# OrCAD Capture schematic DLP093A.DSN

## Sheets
1 PAGE-06 Disclaimer
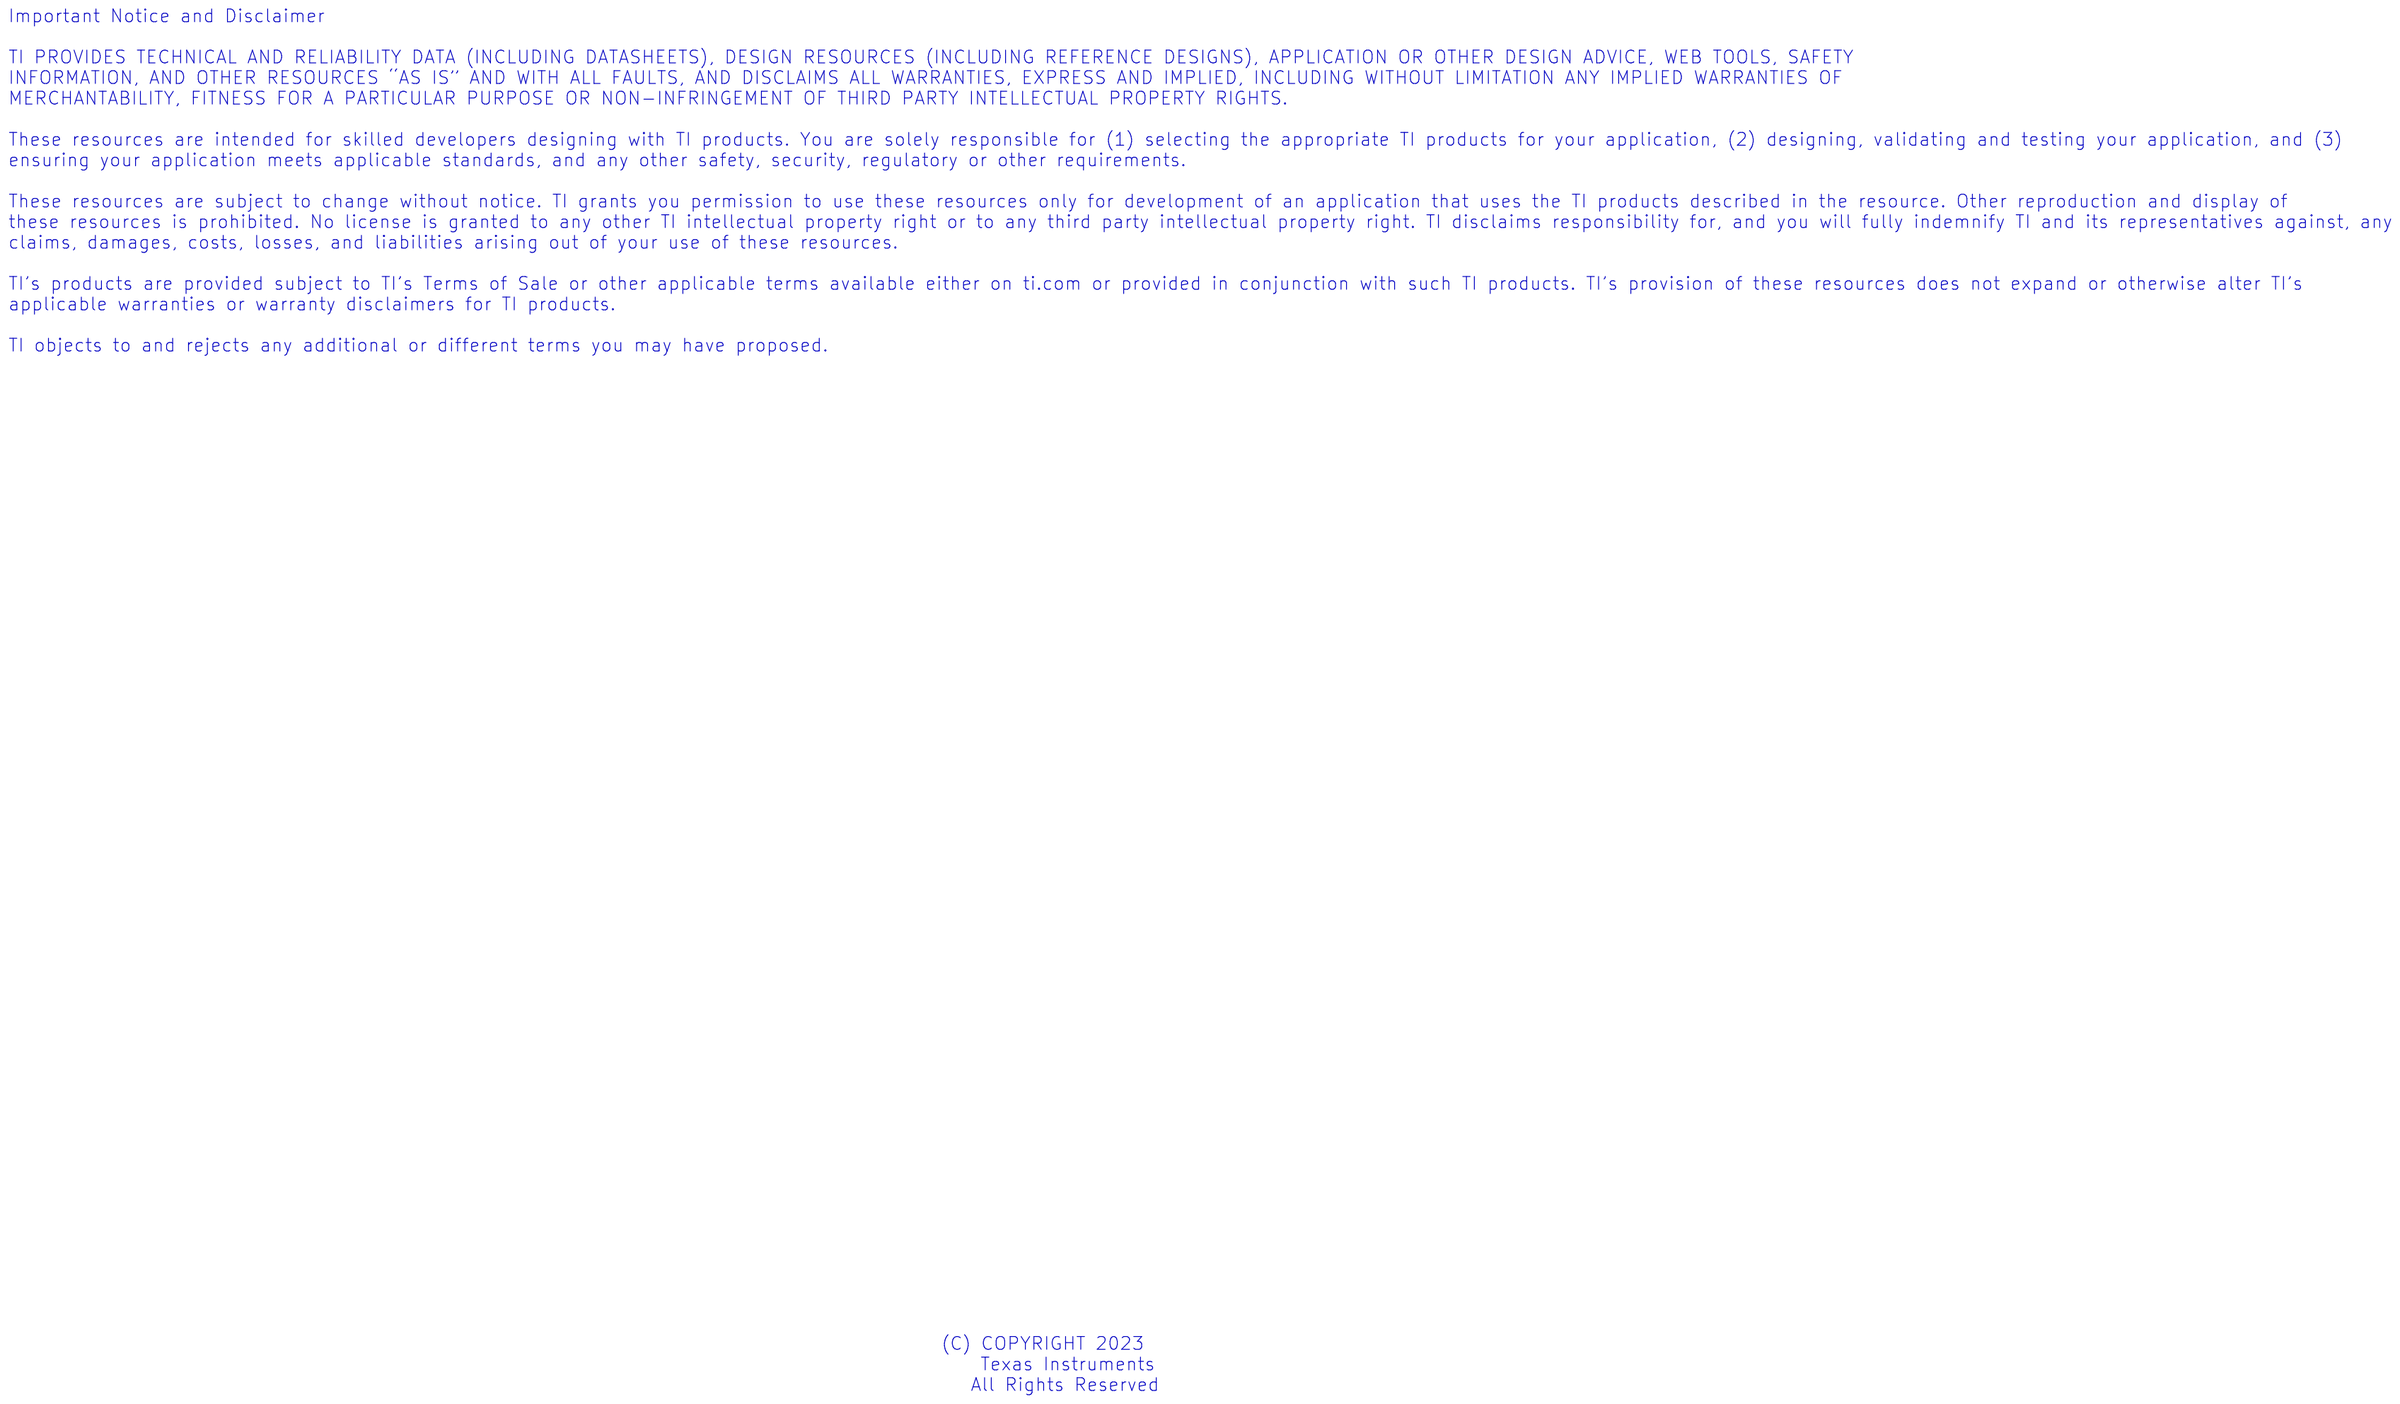
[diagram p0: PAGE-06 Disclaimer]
2 PAGE-05  DLPA200 RESET DRIVER: size A3
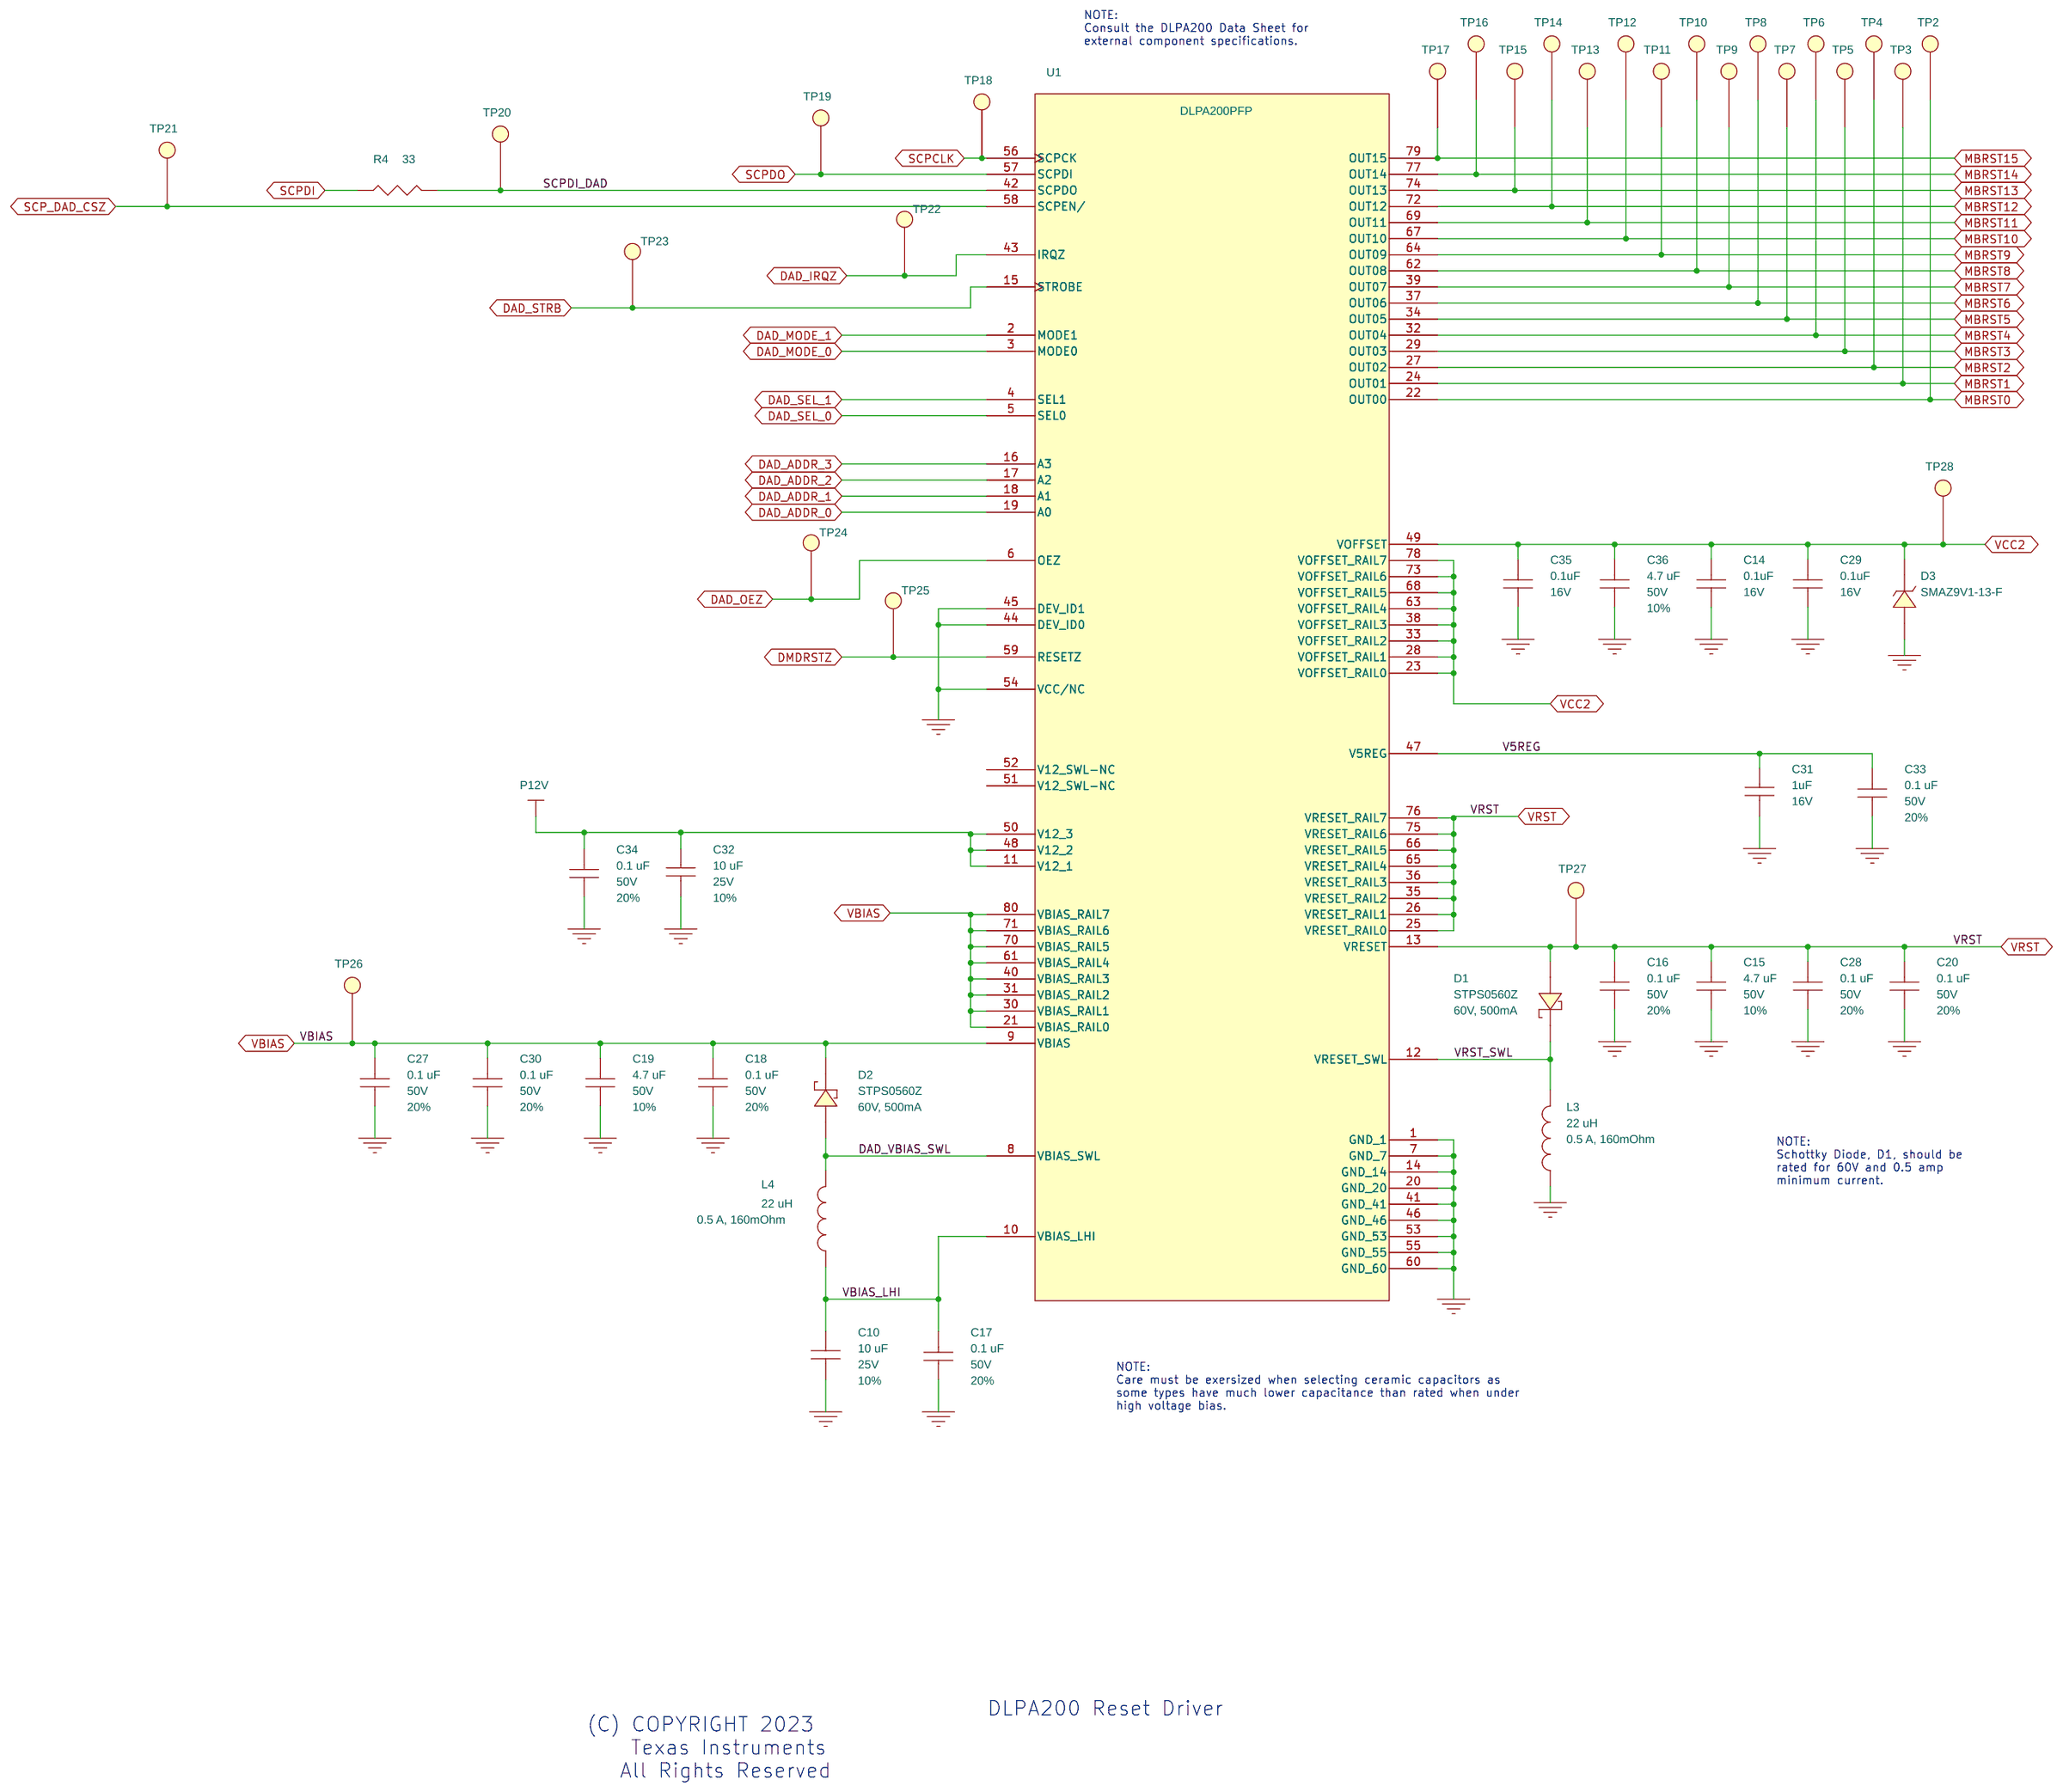
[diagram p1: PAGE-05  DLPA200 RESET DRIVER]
3 PAGE-01  TITLE
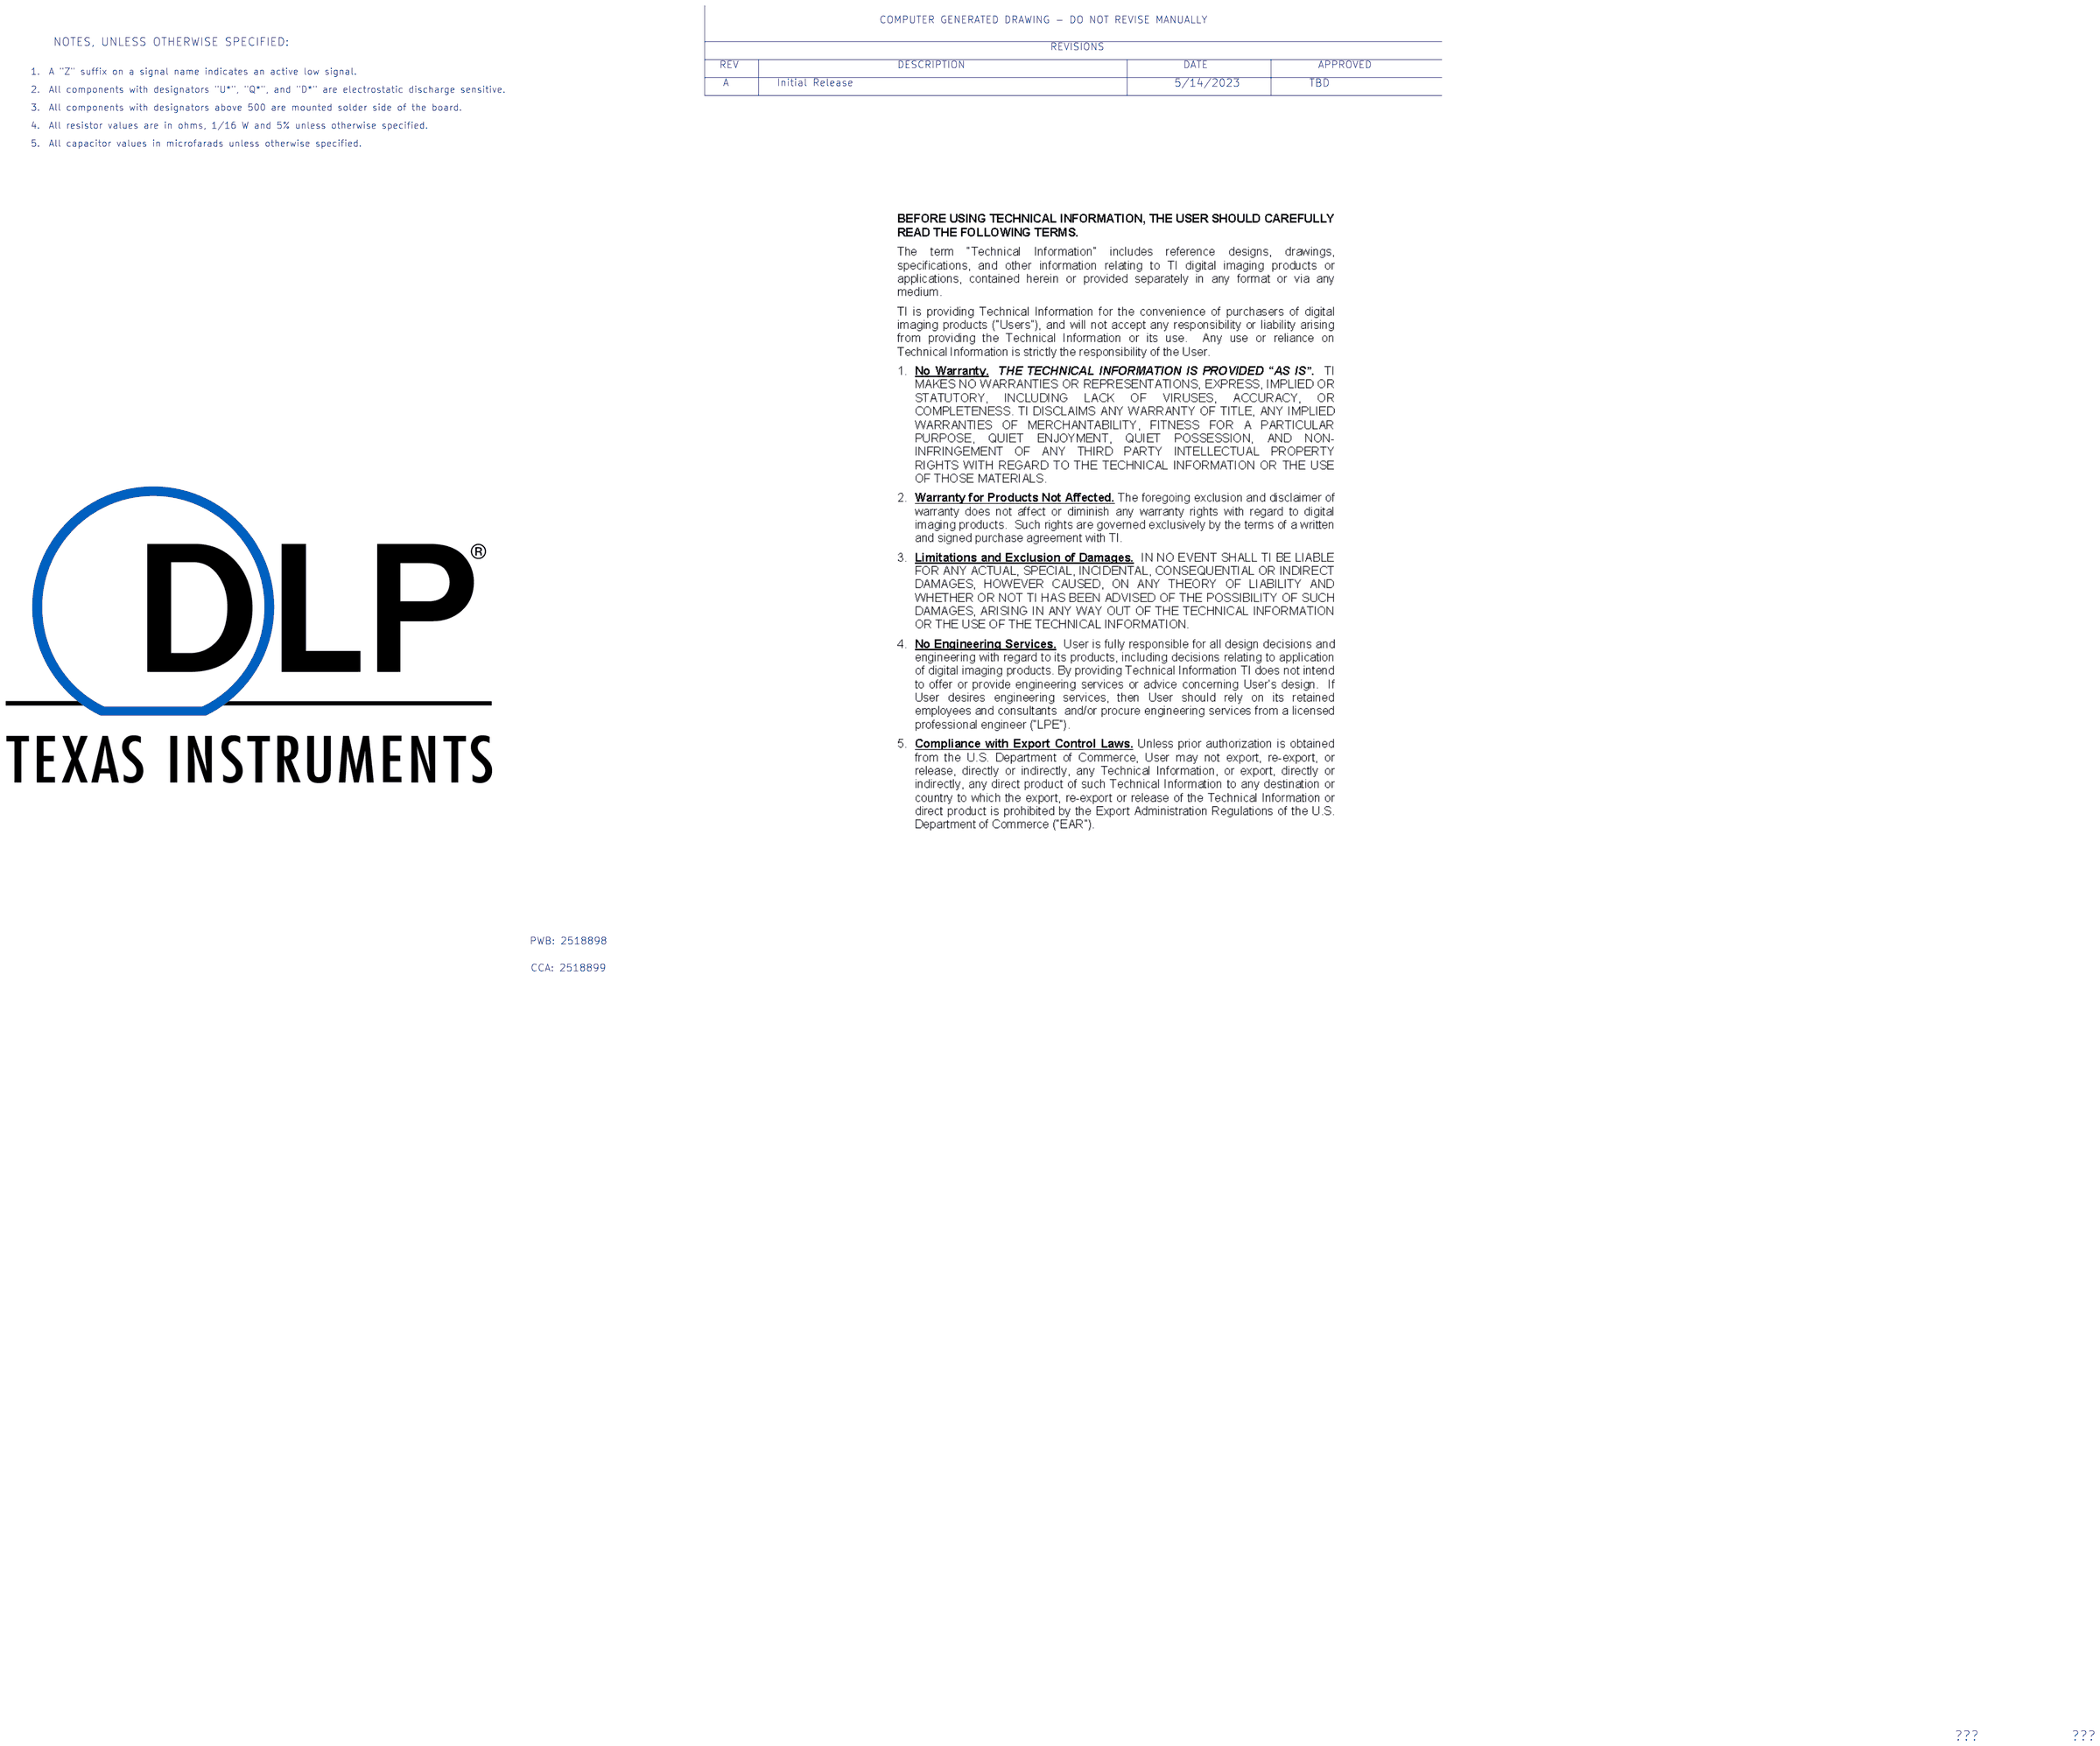
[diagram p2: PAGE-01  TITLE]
4 PAGE-02  Block Diagram
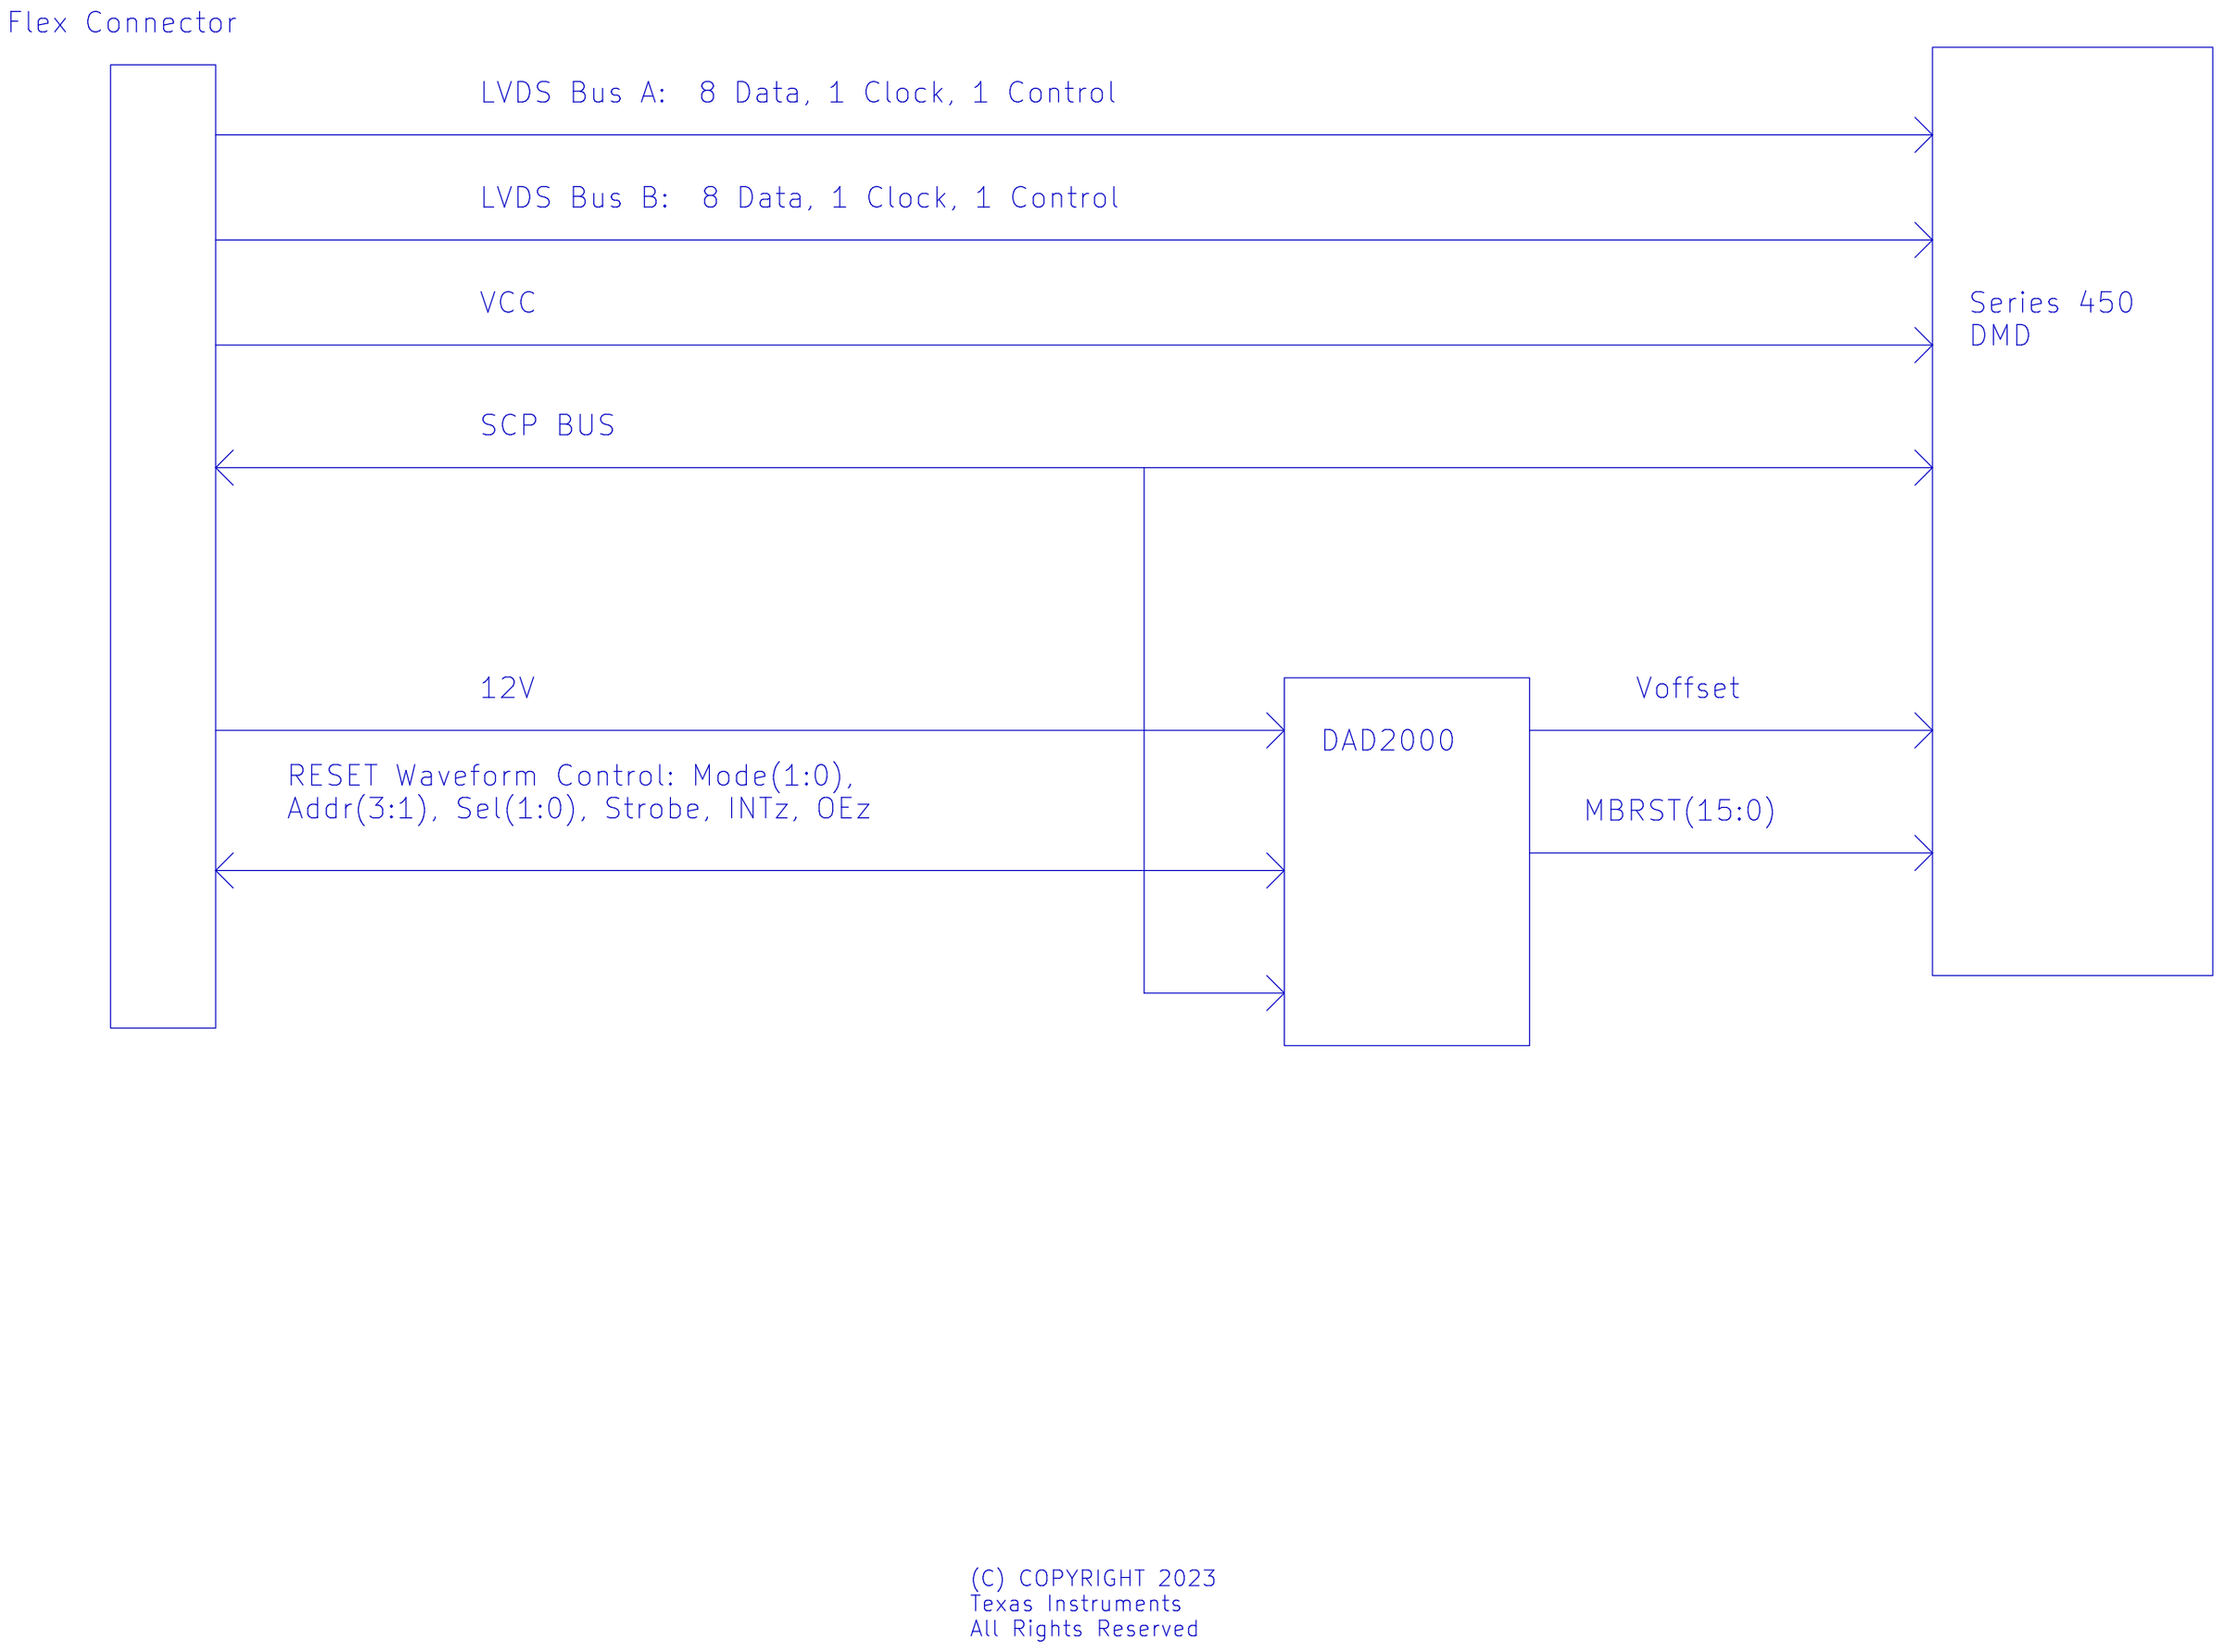
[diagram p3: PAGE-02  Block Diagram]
5 PAGE-04  Series 450 DMD: size A3
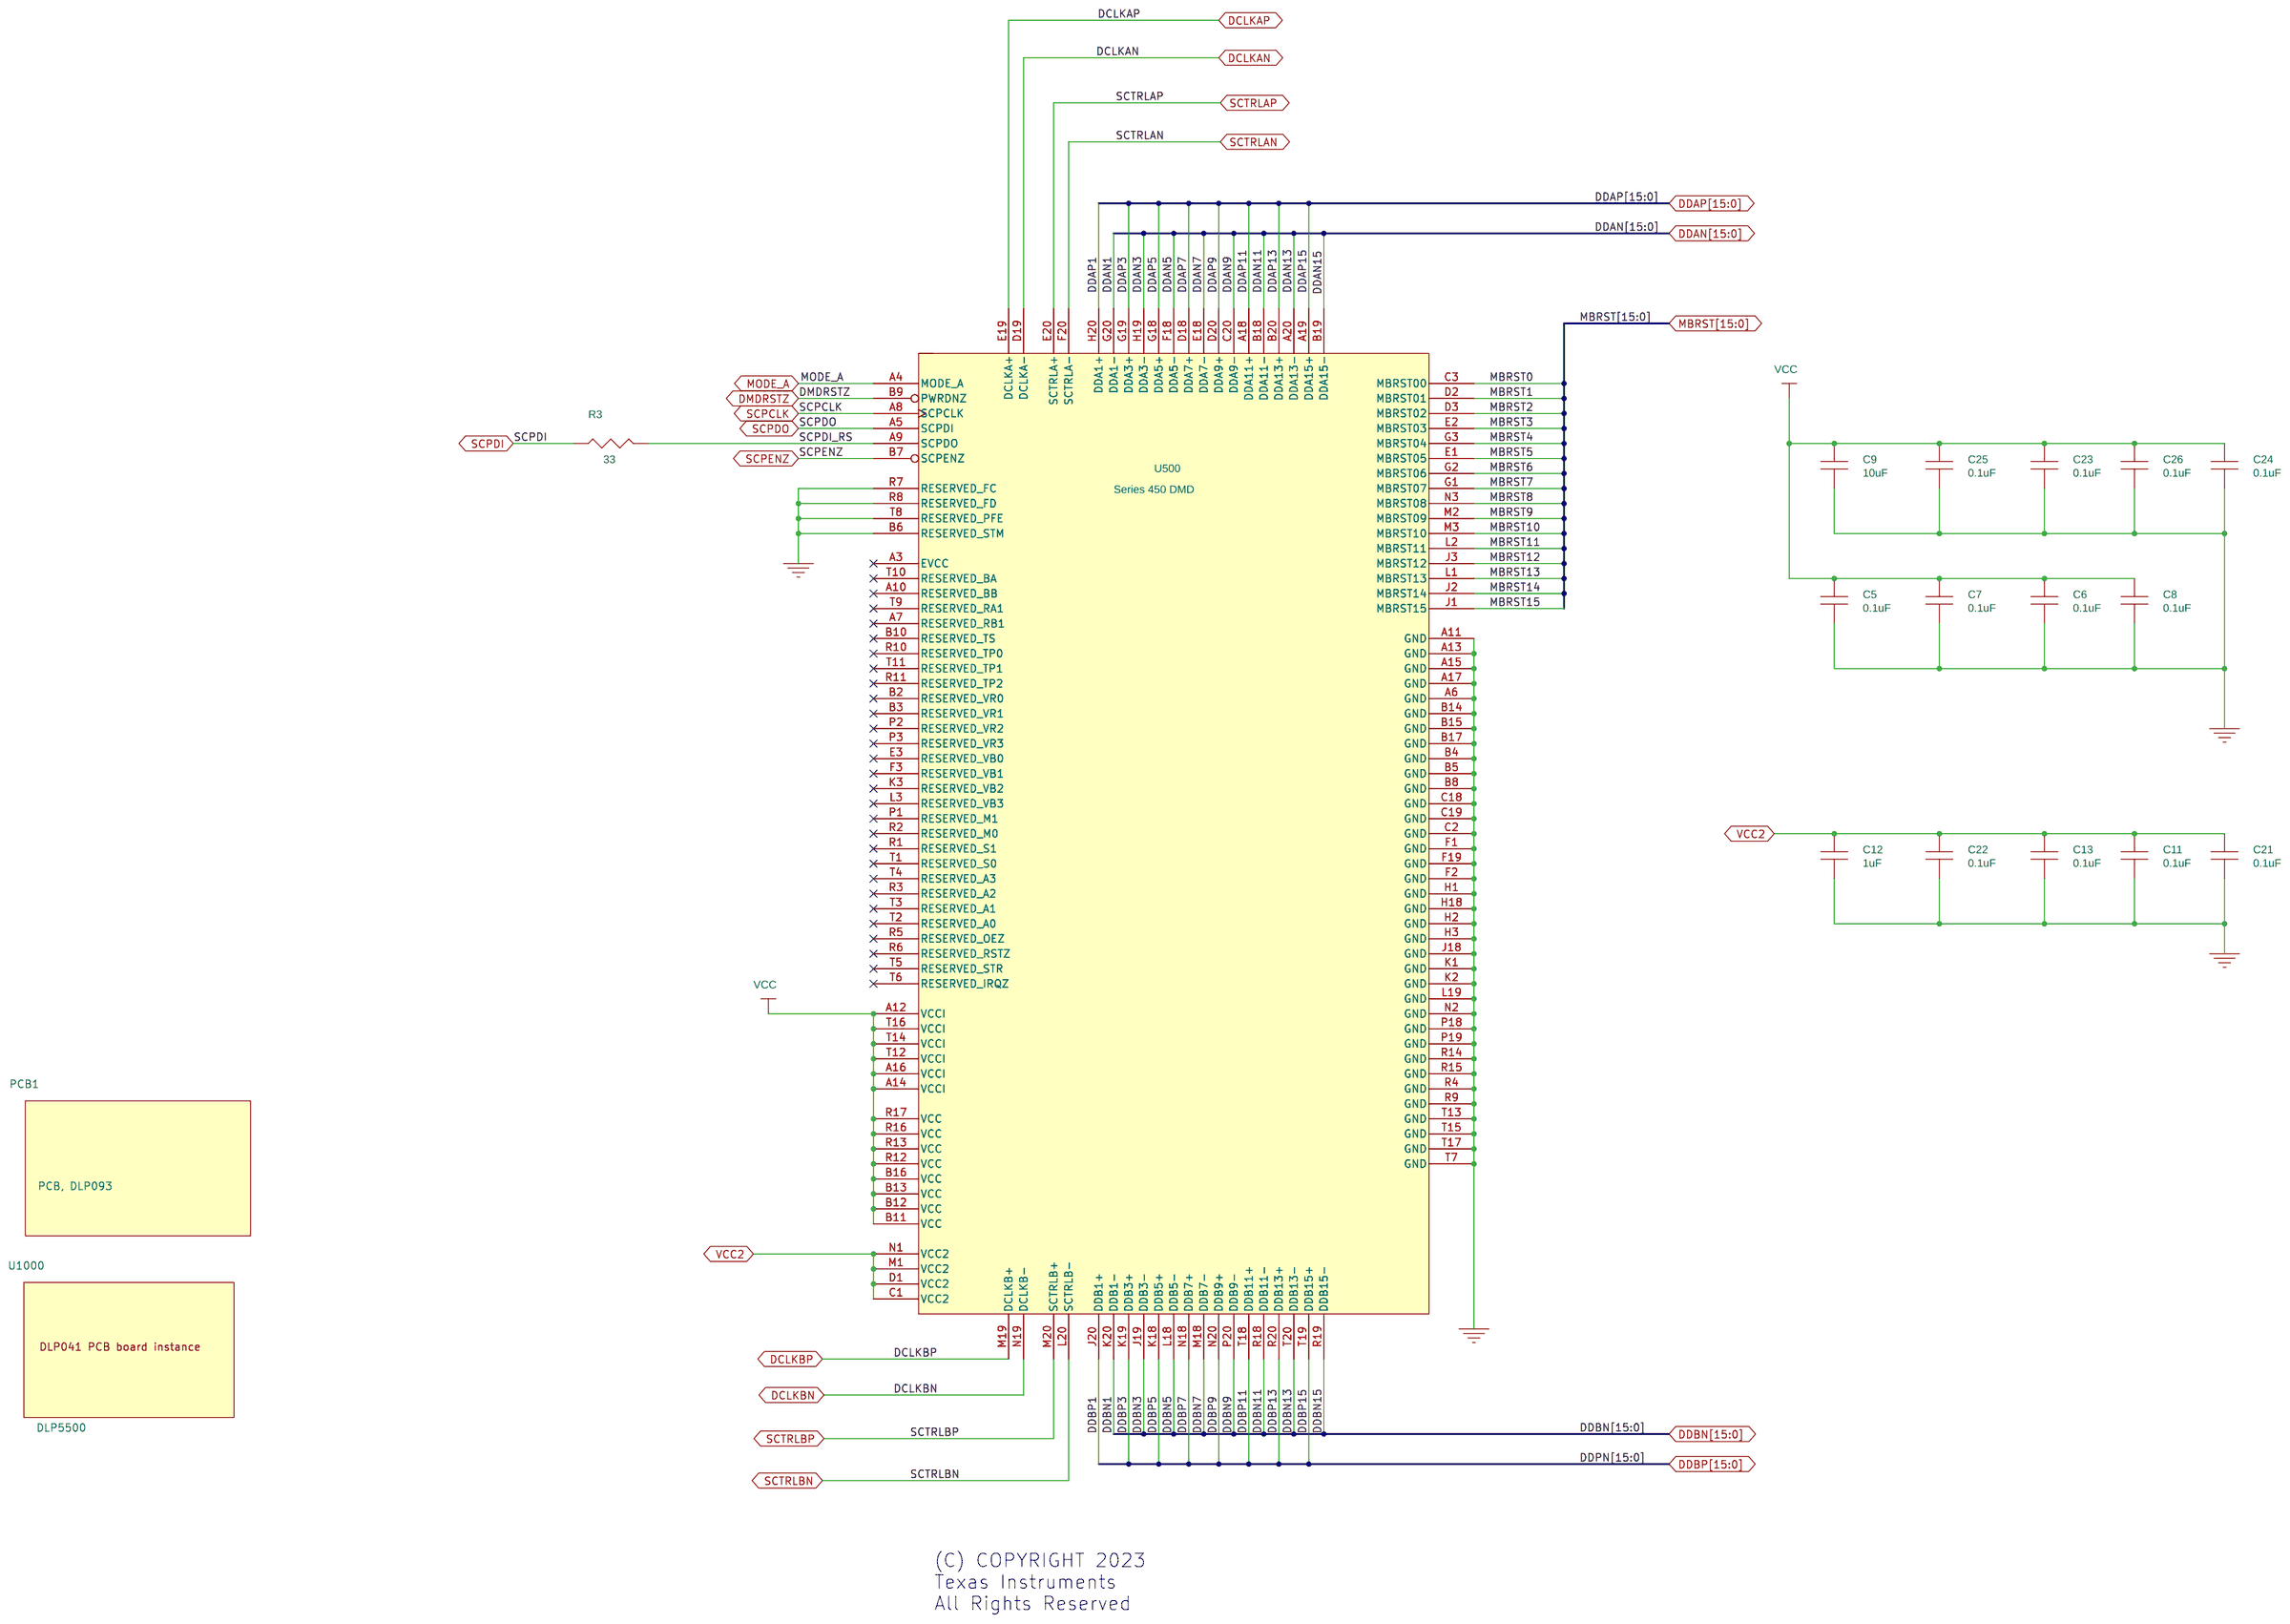
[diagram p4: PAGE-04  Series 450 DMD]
6 PAGE-03  Flex Connector: size A3
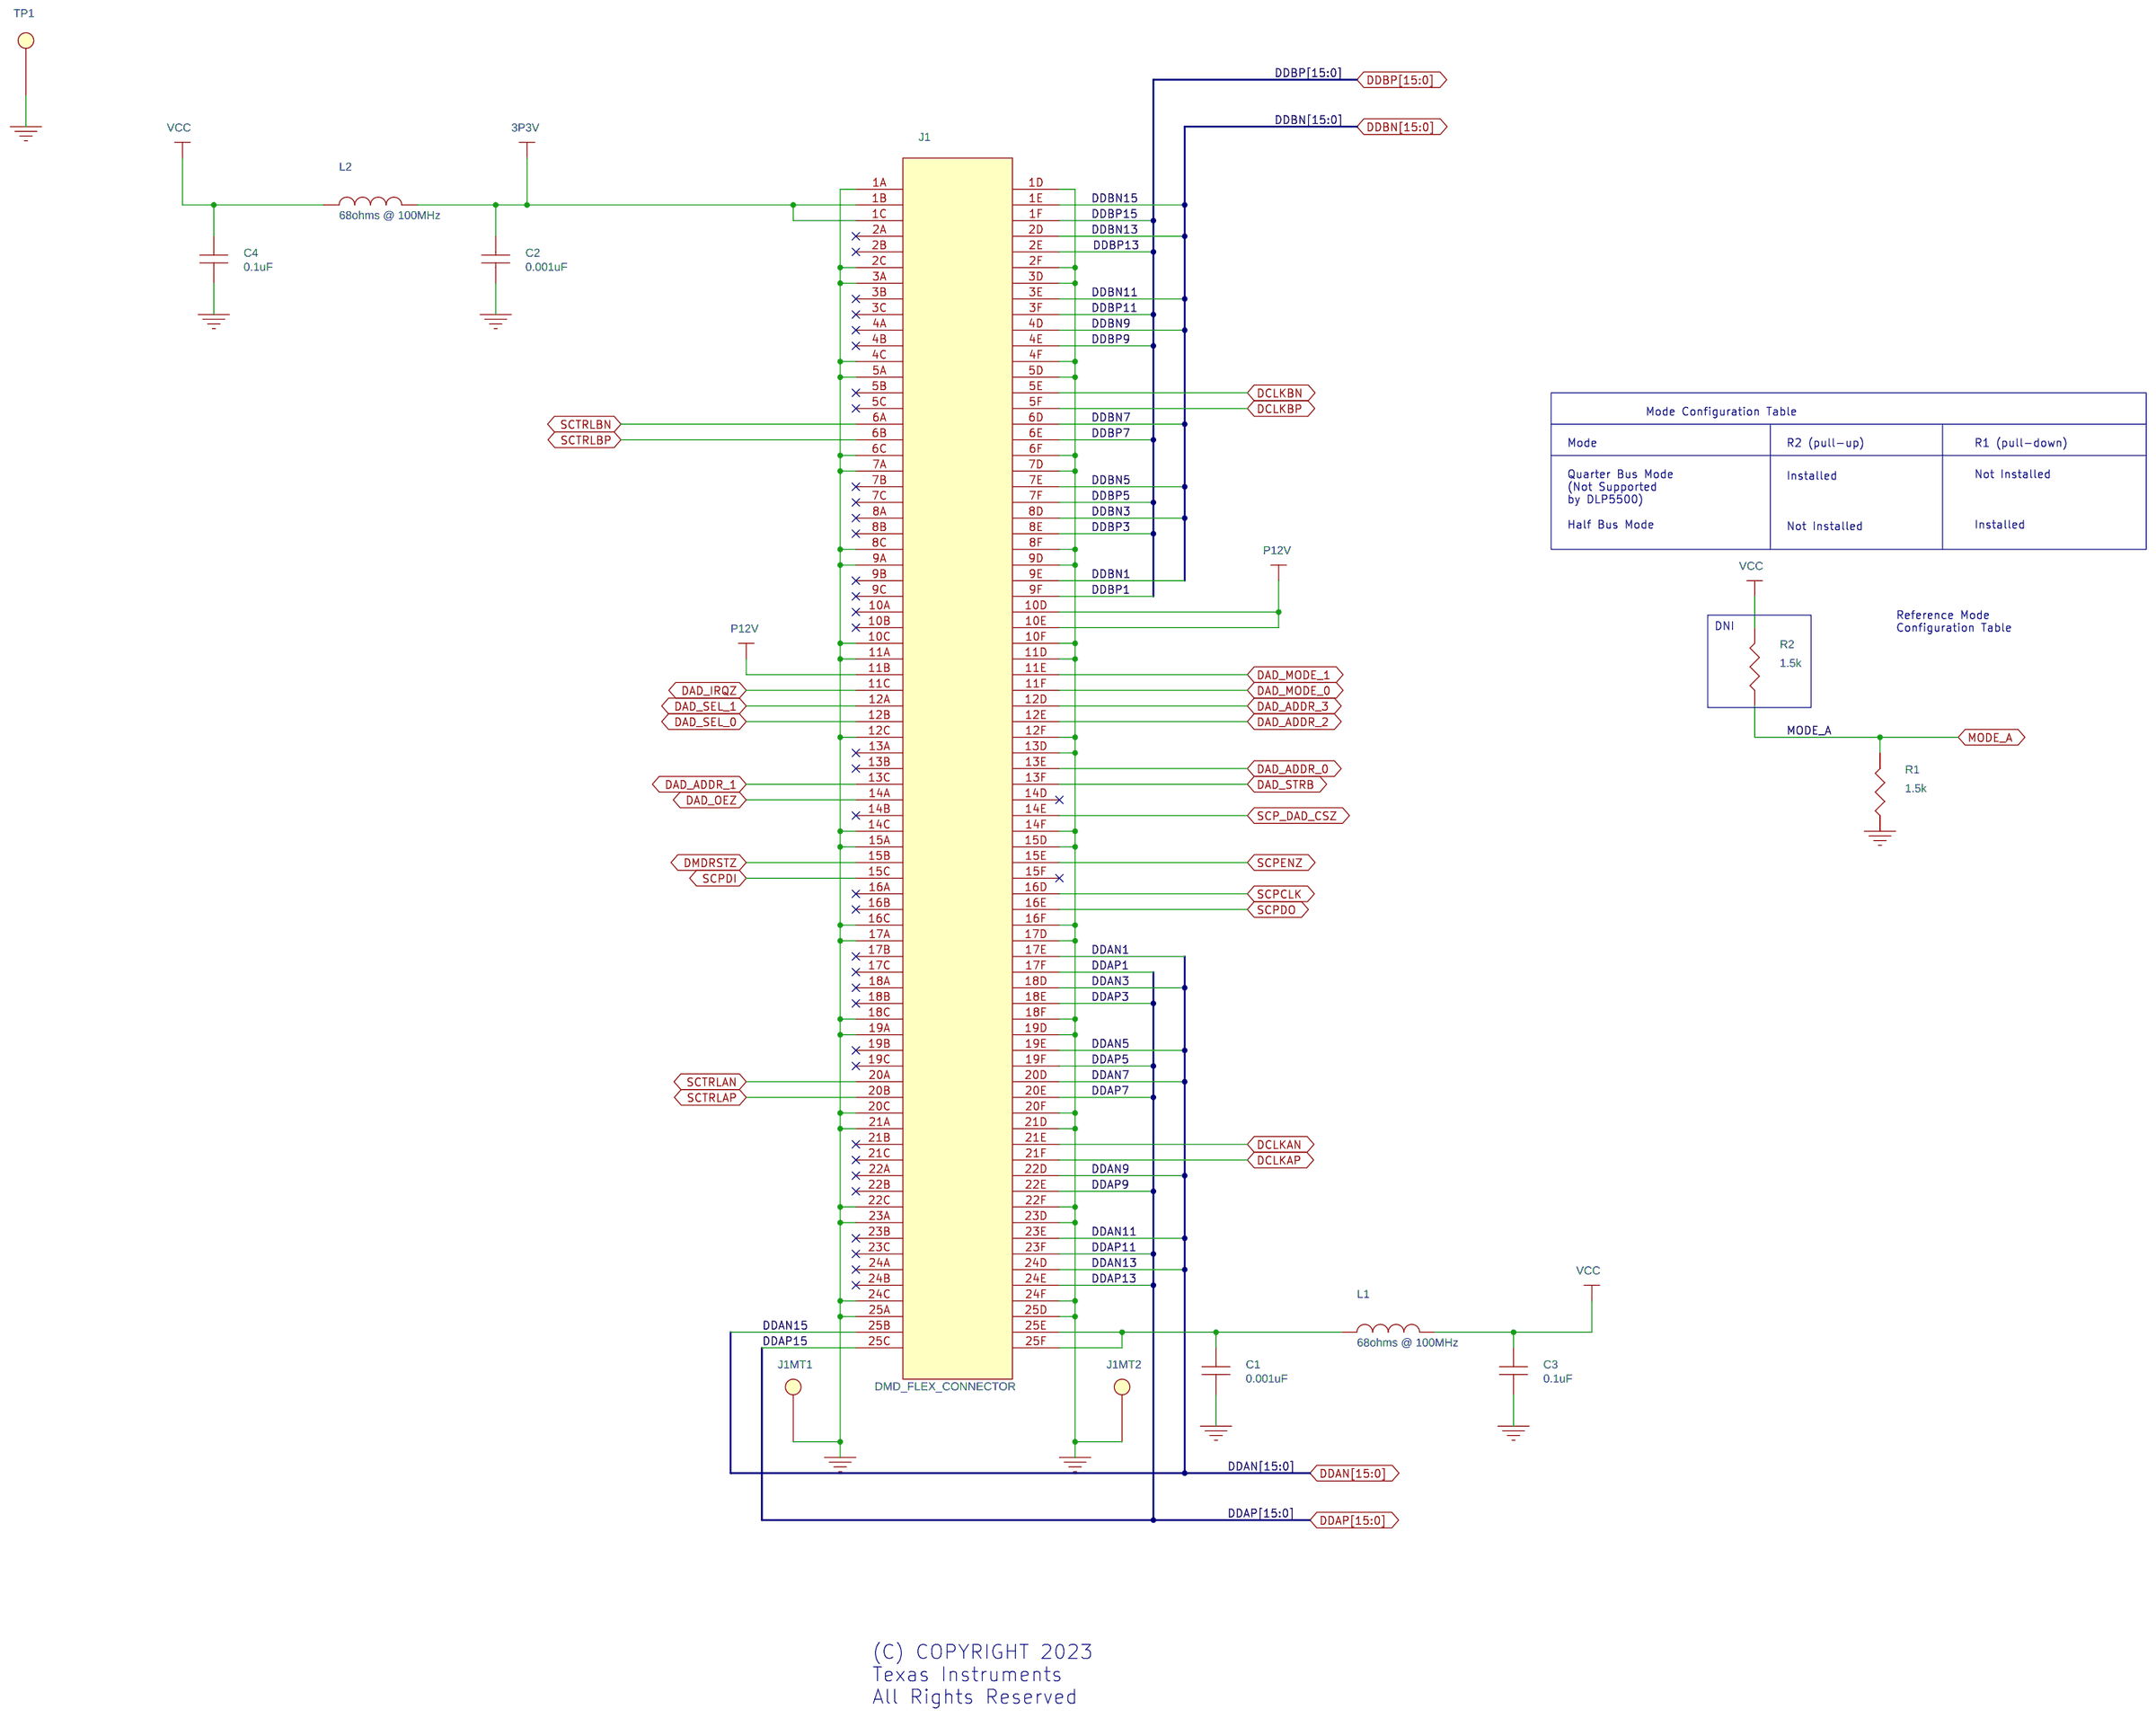
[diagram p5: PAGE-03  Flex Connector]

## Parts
sheet PAGE-03  Flex Connector
C1  0.001uF  [0603AVX]
C2  0.001uF  [0603AVX]
C3  0.1uF  [0603AVX]
C4  0.1uF  [0603AVX]
J1  DMD_FLEX_CONNECTOR  [CN150CUSTOM_REVB]
J1MT1  MT2  [MT2]
J1MT2  MT2  [MT2]
L1  68ohms @ 100MHz  [0603AVX]
L2  68ohms @ 100MHz  [0603AVX]
R1  1.5k  [0603]
R2  1.5k  [0603]
TP1  Testpoint  [TP40_24]
sheet PAGE-04  Series 450 DMD
C5  0.1uF  [0603AVX]
C6  0.1uF  [0603AVX]
C7  0.1uF  [0603AVX]
C8  0.1uF  [0603AVX]
C9  10uF  [1206AVX]
C11  0.1uF  [0603AVX]
C12  1uF  [0603AVX]
C13  0.1uF  [0603AVX]
C21  0.1uF  [0603AVX]
C22  0.1uF  [0603AVX]
C23  0.1uF  [0603AVX]
C24  0.1uF  [0603AVX]
C25  0.1uF  [0603AVX]
C26  0.1uF  [0603AVX]
PCB1  PCB, DLP093
R3  33  [0603AVX]
U500  Series 450 DMD  [DMD_S450]
U1000  DLP5500
sheet PAGE-05  DLPA200 RESET DRIVER
C10  10 uF  [CAP_1210]
C14  0.1uF  [0603AVX]
C15  4.7 uF  [CAP_1812]
C16  0.1 uF  [CAP_0805]
C17  0.1 uF  [CAP_0805]
C18  0.1 uF  [CAP_0805]
C19  4.7 uF  [CAP_1812]
C20  0.1 uF  [CAP_0805]
C27  0.1 uF  [CAP_0805]
C28  0.1 uF  [CAP_0805]
C29  0.1uF  [0603AVX]
C30  0.1 uF  [CAP_0805]
C31  1uF  [0603AVX]
C32  10 uF  [CAP_1210]
C33  0.1 uF  [CAP_0805]
C34  0.1 uF  [CAP_0805]
C35  0.1uF  [0603AVX]
C36  4.7 uF  [CAP_1812]
D1  DIODE_SCHOTTKY  [SOD_123]
D2  DIODE_SCHOTTKY  [SOD_123]
D3  9.1V  [DO-214AC]
L3  22 uH  [IND_DT1608C]
L4  22 uH  [IND_DT1608C]
R4  33  [0603AVX]
TP2  Testpoint  [TP40_24]
TP3  Testpoint  [TP40_24]
TP4  Testpoint  [TP40_24]
TP5  Testpoint  [TP40_24]
TP6  Testpoint  [TP40_24]
TP7  Testpoint  [TP40_24]
TP8  Testpoint  [TP40_24]
TP9  Testpoint  [TP40_24]
TP10  Testpoint  [TP40_24]
TP11  Testpoint  [TP40_24]
TP12  Testpoint  [TP40_24]
TP13  Testpoint  [TP40_24]
TP14  Testpoint  [TP40_24]
TP15  Testpoint  [TP40_24]
TP16  Testpoint  [TP40_24]
TP17  Testpoint  [TP40_24]
TP18  Testpoint  [TP40_24]
TP19  Testpoint  [TP40_24]
TP20  Testpoint  [TP40_24]
TP21  Testpoint  [TP40_24]
TP22  Testpoint  [TP40_24]
TP23  Testpoint  [TP40_24]
TP24  Testpoint  [TP40_24]
TP25  Testpoint  [TP40_24]
TP26  Testpoint  [TP40_24]
TP27  Testpoint  [TP40_24]
TP28  Testpoint  [TP40_24]
U1  DLPA200  [TQFP80_5MM]

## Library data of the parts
C1 C2 = CAP_NP: Capacitor; CCA ITEM: 3; MFG: AVX; Part Number: 06035C102KAT2A; Rating: 50V; Tolerance: 10%; Type: X7R; Vendor: Digi-key
C3-C8 C11 C13 C21-C26 = CAP_NP: Capacitor; CCA ITEM: 1; MFG: AVX; Part Number: 0603YC104KAT2A; Rating: 16V; Tolerance: 10%; Type: X7R; Vendor: Digi-key
J1 = DMD_FLEX_CONNECTOR_2: Connector, Flex; CCA ITEM: 8; MFG: Amphenol; NOT INSTALLED: DNI; Part Number: Not-a-Part; Vendor: N/A
J1MT1 J1MT2 TP2-TP14 = Testpoint: Test point; MFG: Not-a-part; Part Number: Not-a-part; Vendor: Digi-key
L1 L2 = INDUCTOR: Ferrite; CCA ITEM: 11; MFG: Steward; Part Number: MI0603J680R-10; Vendor: Digi-key
R1 = R: Resistor; CCA ITEM: 14; MFG: Yageo; Part Number: RC0603FR-071K5L; Rating: 1/10W; Vendor: Digi-key
R2 = R: Resistor; CCA ITEM: 14; MFG: Yageo; NOT INSTALLED: DNI; Part Number: RC0603FR-071K5L; Rating: 1/10W; Vendor: Digi-key
TP1 = Testpoint: Test point; Part Number: Not-a-part; Vendor: Digi-key
C9 = CAP_NP: Capacitor; CCA ITEM: 7; MFG: Taiyo Yuden; Part Number: TMK316B7106KL-TD; Rating: 10V; Tolerance: 10%; Type: X7R; Vendor: Digi-key
C12 = CAP_NP: Capacitor; CCA ITEM: 6; MFG: Taiyo Yuden; Part Number: EMK107B7105KA-T; Rating: 16V; Tolerance: 10%; Type: X7R; Vendor: Digi-key
PCB1 = PCB_2
R3 R4 = R: Resistor; CCA ITEM: 13; MFG: Yageo; Part Number: RC0603FR-0733RL; Rating: 1/10W; Tolerance: 1%; Vendor: Digi-key
U500 = Series_450_DMD: IC, S450 ZIF DMD Socket; CCA ITEM: 15; MFG: Foxconn Interconnect Tech (FIT); Part Number: PZ14927-1541-01F; Vendor: Digi-key
U1000 = DLP026_0: DMD Instance; MFG: Texas Instruments; Part Number: DLP5500BFYA
C10 C32 = CAP_NP: Capacitor; CCA ITEM: 4; MFG: KEMET; Part Number: C1210C106M3RAC7800; RATING: 25V; TOLERANCE: 10%; Type: X7R; Vendor: Digi-key
C14 C29 C35 = CAP_NP: Capacitor; CCA ITEM: 1; MFG: AVX; Part Number: 0603YC104KAT2A; RATING: 16V; TOLERANCE: 10%; Type: X7R; Vendor: Digi-key
C15 C19 C36 = CAP_NP: Capacitor; CCA ITEM: 5; MFG: KEMET; Part Number: C1812F475K5RAC7800; RATING: 50V; TOLERANCE: 10%; Type: X7R; Vendor: Digi-key
C16-C18 C20 C27 C28 C30 C33 C34 = CAP_NP: Capacitor; CCA ITEM: 2; MFG: AVX; Part Number: 08055C104MAT2A; RATING: 50V; TOLERANCE: 20%; Type: X7R; Vendor: Digi-key
C31 = CAP_NP: Capacitor; CCA ITEM: 6; MFG: Taiyo Yuden; Part Number: EMK107B7105KA-T; RATING: 16V; TOLERANCE: 10%; Type: X7R; Vendor: Digi-key
D1 D2 = DIODE_SCHOTTKY: Diode, Schottky; CCA ITEM: 10; MFG: STMICRO; Part Number: STPS0560Z; RATING: 60V, 500mA; Vendor: Digi-key
D3 = DIODE_ZENER: Diode, Zener; CCA ITEM: 9; MFG: DIODES INC; Part Number: SMAZ9V1-13-F; RATING: 1W; RATING/TOLERANCE: 5%; Tolerance: 5%; Vendor: Digi-key
L3 L4 = INDUCTOR: Inductor; CCA ITEM: 12; ICA_MFR_NAME: STEWARD; ICA_PARTNUM: $$731362$$MI0603J680R-10; MFG: COILCRAFT; Part Number: LPS4018-223MRC; RATING: 0.5 A, 160mOhm; Vendor: Digi-key
TP15-TP28 = Testpoint: Test point - Probe Tip; MFG: Not-a-part; Part Number: Not-a-part; Vendor: Digi-key
U1 = DAD2000: IC, DMD Power and Reset; CCA ITEM: 16; MFG: Texas Instruments; Part Number: DLPA200PFP; Vendor: Digi-key

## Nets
GND: C1.2 C2.2 C3.2 C4.2 C5.2 C6.2 C7.2 C8.2 C9.2 C10.2 C11.2 C12.2 C13.2 C14.1 C15.1 C16.1 C17.1 C18.1 C19.1 C20.1 C21.2 C22.2 C23.2 C24.2 C25.2 C26.2 C27.1 C28.1 C29.1 C30.1 C31.2 C32.2 C33.1 C34.1 C35.1 C36.1 D3.2(ANODE) J1.1A J1.1D J1.2C J1.2F J1.3A J1.3D J1.4C J1.4F J1.5A J1.5D J1.6C J1.6F J1.7A J1.7D J1.8C J1.8F J1.9A J1.9D J1.10C J1.10F J1.11A J1.11D J1.12C J1.12F J1.13D J1.14C J1.14F J1.15A J1.15D J1.16C J1.16F J1.17A J1.17D J1.18C J1.18F J1.19A J1.19D J1.20C J1.20F J1.21A J1.21D J1.22C J1.22F J1.23A J1.23D J1.24C J1.24F J1.25A J1.25D J1MT1.1 J1MT2.1 L3.1 R1.1 TP1.1 U1.1(GND) U1.7(GND) U1.14(GND) U1.20(GND) U1.41(GND) U1.44(DEV_ID0) U1.45(DEV_ID1) U1.46(GND) U1.53(GND) U1.54(VCC/NC) U1.55(GND) U1.60(GND) U500.A6(GND) U500.A11(GND) U500.A13(GND) U500.A15(GND) U500.A17(GND) U500.B4(GND) U500.B5(GND) U500.B6(RESERVED_STM) U500.B8(GND) U500.B14(GND) U500.B15(GND) U500.B17(GND) U500.C2(GND) U500.C18(GND) U500.C19(GND) U500.F1(GND) U500.F2(GND) U500.F19(GND) U500.H1(GND) U500.H2(GND) U500.H3(GND) U500.H18(GND) U500.J18(GND) U500.K1(GND) U500.K2(GND) U500.L19(GND) U500.N2(GND) U500.P18(GND) U500.P19(GND) U500.R4(GND) U500.R7(RESERVED_FC) U500.R8(RESERVED_FD) U500.R9(GND) U500.R14(GND) U500.R15(GND) U500.T7(GND) U500.T8(RESERVED_PFE) U500.T13(GND) U500.T15(GND) U500.T17(GND)
P12V: C32.1 C34.2 J1.10D J1.10E J1.11B U1.11(V12_1) U1.48(V12_2) U1.50(V12_3)
V5REG: C31.1 C33.2 U1.47(V5REG)
V12_SWL-NC: U1.51(V12_SWL-NC) U1.52(V12_SWL-NC)
VCC: C3.1 C4.1 C5.1 C6.1 C7.1 C8.1 C9.1 C23.1 C24.1 C25.1 C26.1 L1.2 L2.1 R2.2 U500.A12(VCCI) U500.A14(VCCI) U500.A16(VCCI) U500.B11(VCC) U500.B12(VCC) U500.B13(VCC) U500.B16(VCC) U500.R12(VCC) U500.R13(VCC) U500.R16(VCC) U500.R17(VCC) U500.T12(VCCI) U500.T14(VCCI) U500.T16(VCCI)
VCC2: C11.1 C12.1 C13.1 C14.2 C21.1 C22.1 C29.2 C35.2 C36.2 D3.1(CATHODE) TP28.1 U1.23(VOFFSET_RAIL0) U1.28(VOFFSET_RAIL1) U1.33(VOFFSET_RAIL2) U1.38(VOFFSET_RAIL3) U1.49(VOFFSET) U1.63(VOFFSET_RAIL4) U1.68(VOFFSET_RAIL5) U1.73(VOFFSET_RAIL6) U1.78(VOFFSET_RAIL7) U500.C1(VCC2) U500.D1(VCC2) U500.M1(VCC2) U500.N1(VCC2)
3P3V: C2.1 J1.1B J1.1C L2.2
DAD_ADDR_0: J1.13E U1.19(A0)
DAD_ADDR_1: J1.13C U1.18(A1)
DAD_ADDR_2: J1.12E U1.17(A2)
DAD_ADDR_3: J1.12D U1.16(A3)
DAD_IRQZ: J1.11C TP22.1 U1.43(IRQZ)
DAD_MODE_0: J1.11F U1.3(MODE0)
DAD_MODE_1: J1.11E U1.2(MODE1)
DAD_OEZ: J1.14A TP24.1 U1.6(OEZ)
DAD_SEL_0: J1.12B U1.5(SEL0)
DAD_SEL_1: J1.12A U1.4(SEL1)
DAD_STRB: J1.13F TP23.1 U1.15(STROBE)
DAD_VBIAS_SWL: D2.2(A) L4.2 U1.8(VBIAS_SWL)
DCLKAN: J1.21E U500.D19(DCLKA-)
DCLKAP: J1.21F U500.E19(DCLKA+)
DCLKBN: J1.5E U500.N19(DCLKB-)
DCLKBP: J1.5F U500.M19(DCLKB+)
DDAN1: J1.17E U500.G20(DDA1-)
DDAN3: J1.18D U500.H19(DDA3-)
DDAN5: J1.19E U500.F18(DDA5-)
DDAN7: J1.20D U500.E18(DDA7-)
DDAN9: J1.22D U500.C20(DDA9-)
DDAN11: J1.23E U500.B18(DDA11-)
DDAN13: J1.24D U500.A20(DDA13-)
DDAN15: J1.25B U500.B19(DDA15-)
DDAP1: J1.17F U500.H20(DDA1+)
DDAP3: J1.18E U500.G19(DDA3+)
DDAP5: J1.19F U500.G18(DDA5+)
DDAP7: J1.20E U500.D18(DDA7+)
DDAP9: J1.22E U500.D20(DDA9+)
DDAP11: J1.23F U500.A18(DDA11+)
DDAP13: J1.24E U500.B20(DDA13+)
DDAP15: J1.25C U500.A19(DDA15+)
DDBN1: J1.9E U500.K20(DDB1-)
DDBN3: J1.8D U500.J19(DDB3-)
DDBN5: J1.7E U500.L18(DDB5-)
DDBN7: J1.6D U500.M18(DDB7-)
DDBN9: J1.4D U500.P20(DDB9-)
DDBN11: J1.3E U500.R18(DDB11-)
DDBN13: J1.2D U500.T20(DDB13-)
DDBN15: J1.1E U500.R19(DDB15-)
DDBP1: J1.9F U500.J20(DDB1+)
DDBP3: J1.8E U500.K19(DDB3+)
DDBP5: J1.7F U500.K18(DDB5+)
DDBP7: J1.6E U500.N18(DDB7+)
DDBP9: J1.4E U500.N20(DDB9+)
DDBP11: J1.3F U500.T18(DDB11+)
DDBP13: J1.2E U500.R20(DDB13+)
DDBP15: J1.1F U500.T19(DDB15+)
DMDRSTZ: J1.15B TP25.1 U1.59(RESETZ) U500.B9(PWRDNZ)
MBRST0: TP2.1 U1.22(OUT00) U500.C3(MBRST00)
MBRST1: TP3.1 U1.24(OUT01) U500.D2(MBRST01)
MBRST2: TP4.1 U1.27(OUT02) U500.D3(MBRST02)
MBRST3: TP5.1 U1.29(OUT03) U500.E2(MBRST03)
MBRST4: TP6.1 U1.32(OUT04) U500.G3(MBRST04)
MBRST5: TP7.1 U1.34(OUT05) U500.E1(MBRST05)
MBRST6: TP8.1 U1.37(OUT06) U500.G2(MBRST06)
MBRST7: TP9.1 U1.39(OUT07) U500.G1(MBRST07)
MBRST8: TP10.1 U1.62(OUT08) U500.N3(MBRST08)
MBRST9: TP11.1 U1.64(OUT09) U500.M2(MBRST09)
MBRST10: TP12.1 U1.67(OUT10) U500.M3(MBRST10)
MBRST11: TP13.1 U1.69(OUT11) U500.L2(MBRST11)
MBRST12: TP14.1 U1.72(OUT12) U500.J3(MBRST12)
MBRST13: TP15.1 U1.74(OUT13) U500.L1(MBRST13)
MBRST14: TP16.1 U1.77(OUT14) U500.J2(MBRST14)
MBRST15: TP17.1 U1.79(OUT15) U500.J1(MBRST15)
MODE_A: R1.2 R2.1 U500.A4(MODE_A)
SCP_DAD_CSZ: J1.14E TP21.1 U1.58(SCPEN/)
SCPCLK: J1.16D TP18.1 U1.56(SCPCK) U500.A8(SCPCLK)
SCPDI: J1.15C R3.1 R4.1
SCPDI_DAD: R4.2 TP20.1 U1.42(SCPDO)
SCPDI_RS: R3.2 U500.A9(SCPDO)
SCPDO: J1.16E TP19.1 U1.57(SCPDI) U500.A5(SCPDI)
SCPENZ: J1.15E U500.B7(SCPENZ)
SCTRLAN: J1.20A U500.F20(SCTRLA-)
SCTRLAP: J1.20B U500.E20(SCTRLA+)
SCTRLBN: J1.6A U500.L20(SCTRLB-)
SCTRLBP: J1.6B U500.M20(SCTRLB+)
VBIAS: C18.2 C19.2 C27.2 C30.2 D2.1(C) TP26.1 U1.9(VBIAS) U1.21(VBIAS_RAIL0) U1.30(VBIAS_RAIL1) U1.31(VBIAS_RAIL2) U1.40(VBIAS_RAIL3) U1.61(VBIAS_RAIL4) U1.70(VBIAS_RAIL5) U1.71(VBIAS_RAIL6) U1.80(VBIAS_RAIL7)
VBIAS_LHI: C10.1 C17.2 L4.1 U1.10(VBIAS_LHI)
VRST: C15.2 C16.2 C20.2 C28.2 D1.2(A) TP27.1 U1.13(VRESET) U1.25(VRESET_RAIL0) U1.26(VRESET_RAIL1) U1.35(VRESET_RAIL2) U1.36(VRESET_RAIL3) U1.65(VRESET_RAIL4) U1.66(VRESET_RAIL5) U1.75(VRESET_RAIL6) U1.76(VRESET_RAIL7)
VRST_SWL: D1.1(C) L3.2 U1.12(VRESET_SWL)
N28103: C1.1 J1.25E J1.25F L1.1

Not connected (* = marked no-connect by the designer): J1 2A* 2B* 3B* 3C* 4A* 4B* 5B* 5C* 7B* 7C* 8A* 8B* 9B* 9C* 10A* 10B* 13A* 13B* 14B* 14D* 15F* 16A* 16B* 17B* 17C* 18A* 18B* 19B* 19C* 21B* 21C* 22A* 22B* 23B* 23C* 24A* 24B*; U500 A3(EVCC)* A7(RESERVED_RB1)* A10(RESERVED_BB)* B2(RESERVED_VR0)* B3(RESERVED_VR1)* B10(RESERVED_TS)* E3(RESERVED_VB0)* F3(RESERVED_VB1)* K3(RESERVED_VB2)* L3(RESERVED_VB3)* P1(RESERVED_M1)* P2(RESERVED_VR2)* P3(RESERVED_VR3)* R1(RESERVED_S1)* R2(RESERVED_M0)* R3(RESERVED_A2)* R5(RESERVED_OEZ)* R6(RESERVED_RSTZ)* R10(RESERVED_TP0)* R11(RESERVED_TP2)* T1(RESERVED_S0)* T2(RESERVED_A0)* T3(RESERVED_A1)* T4(RESERVED_A3)* T5(RESERVED_STR)* T6(RESERVED_IRQZ)* T9(RESERVED_RA1)* T10(RESERVED_BA)* T11(RESERVED_TP1)*

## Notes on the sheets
sheet 1
- Important Notice and Disclaimer
  TI PROVIDES TECHNICAL AND RELIABILITY DATA (INCLUDING DATASHEETS), DESIGN RESOURCES (INCLUDING REFERENCE DESIGNS), APPLICATION OR OTHER DESIGN ADVICE, WEB TOOLS, SAFETY
  INFORMATION, AND OTHER RESOURCES “AS IS” AND WITH ALL FAULTS, AND DISCLAIMS ALL WARRANTIES, EXPRESS AND IMPLIED, INCLUDING WITHOUT LIMITATION ANY IMPLIED WARRANTIES OF
  MERCHANTABILITY, FITNESS FOR A PARTICULAR PURPOSE OR NON-INFRINGEMENT OF THIRD PARTY INTELLECTUAL PROPERTY RIGHTS.
  These resources are intended for skilled developers designing with TI products. You are solely responsible for (1) selecting the appropriate TI products for your application, (2) designing, validating and testing your application, and (3)
  ensuring your application meets applicable standards, and any other safety, security, regulatory or other requirements.
  These resources are subject to change without notice. TI grants you permission to use these resources only for development of an application that uses the TI products described in the resource. Other reproduction and display of
  these resources is prohibited. No license is granted to any other TI intellectual property right or to any third party intellectual property right. TI disclaims responsibility for, and you will fully indemnify TI and its representatives against, any
  claims, damages, costs, losses, and liabilities arising out of your use of these resources.
  TI’s products are provided subject to TI’s Terms of Sale or other applicable terms available either on ti.com or provided in conjunction with such TI products. TI’s provision of these resources does not expand or otherwise alter TI’s
  applicable warranties or warranty disclaimers for TI products.
  TI objects to and rejects any additional or different terms you may have proposed.
- (C) COPYRIGHT 2023
         Texas Instruments
        All Rights Reserved
sheet 2
- NOTE:
  Consult the DLPA200 Data Sheet for
  external component specifications.
- NOTE:
  Schottky Diode, D1, should be
  rated for 60V and 0.5 amp
  minimum current.
- NOTE:
  Care must be exersized when selecting ceramic capacitors as
  some types have much lower capacitance than rated when under
  high voltage bias.
- DLPA200 Reset Driver
- (C) COPYRIGHT 2023
         Texas Instruments
        All Rights Reserved
sheet 3
- COMPUTER GENERATED DRAWING - DO NOT REVISE MANUALLY
- NOTES, UNLESS OTHERWISE SPECIFIED:
- REVISIONS
- REV
- DESCRIPTION
- DATE
- APPROVED
- 1.
- A "Z" suffix on a signal name indicates an active low signal.
- A
- Initial Release
- 5/14/2023
- TBD
- 2.
- All components with designators "U*", "Q*", and "D*" are electrostatic discharge sensitive.
- 3.
- All components with designators above 500 are mounted solder side of the board.
- 4.
- All resistor values are in ohms, 1/16 W and 5% unless otherwise specified.
- 5.
- All capacitor values in microfarads unless otherwise specified.
- PWB: 2518898
- CCA: 2518899
- ???
- ???
sheet 4
- Flex Connector
- LVDS Bus A:  8 Data, 1 Clock, 1 Control
- LVDS Bus B:  8 Data, 1 Clock, 1 Control
- VCC
- Series 450
  DMD
- SCP BUS
- 12V
- Voffset
- DAD2000
- RESET Waveform Control: Mode(1:0),
  Addr(3:1), Sel(1:0), Strobe, INTz, OEz
- MBRST(15:0)
- (C) COPYRIGHT 2023
  Texas Instruments
  All Rights Reserved
sheet 5
- (C) COPYRIGHT 2023
  Texas Instruments
  All Rights Reserved
sheet 6
- Mode Configuration Table
- Mode
- R2 (pull-up)
- R1 (pull-down)
- Quarter Bus Mode
  (Not Supported
  by DLP5500)
  Half Bus Mode
- Not Installed
  Installed
- Installed
  Not Installed
- Reference Mode
  Configuration Table
- DNI
- (C) COPYRIGHT 2023
  Texas Instruments
  All Rights Reserved
